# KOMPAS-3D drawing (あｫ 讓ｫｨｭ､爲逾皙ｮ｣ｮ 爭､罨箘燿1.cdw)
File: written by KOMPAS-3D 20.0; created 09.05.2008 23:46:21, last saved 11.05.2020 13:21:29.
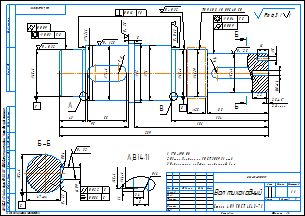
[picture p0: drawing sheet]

Sheet 1: A3, landscape

Document properties: Знак неуказанной шероховатости: 4; Параметр неуказанной шероховатости: Ra 6,3; Полное имя файла: C:\Users\Пользователь\Downloads\Вал цилиндрического редуктора1.cdw

Title block, sheet 1: Наименование: Вал тихоходный; designation: ДМ 413-01.00.11; Материал: Сталь 40Х ГОСТ 4543-71; scale: 1:1; Количество листов документа: 1; Форматы листов документа: A3; stored path: C:\Documents and Settings\Нина\Рабочий стол\Новая папка\Вал.cdw
Table, sheet 1:
  1746997879

Views: Выносной элемент, Вид 3, Вид 4, Вид 7, Выносной элемент А
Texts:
  2.Общие допуски по ГОСТ 30893.1 -mk
  3.Неуказанные радиусы скруглений 1 мм.
  Ra 2,5
  Ra 0,32
  Ra 1,25
  ТВЧ h0.8...1.0 HRC 40...50
  Ra 0,63
  Symbol
  Ra 3,2
  Ra 6,3
  Ra 6,3 ( )
  gliv
Dimensions and other numbers on the sheet: 0,022; 0,086; 1. 170-190 НВ; 0,009; 0,016; 8; 2,5; 2 фаски; 85; 134; 43; 95; 289; 186; 82; 76; 65; 16; 22; -6h; 5; 25; 53; 47; 55; 11; 64; 1.6; 3,4; 1,1; 1:1; 1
